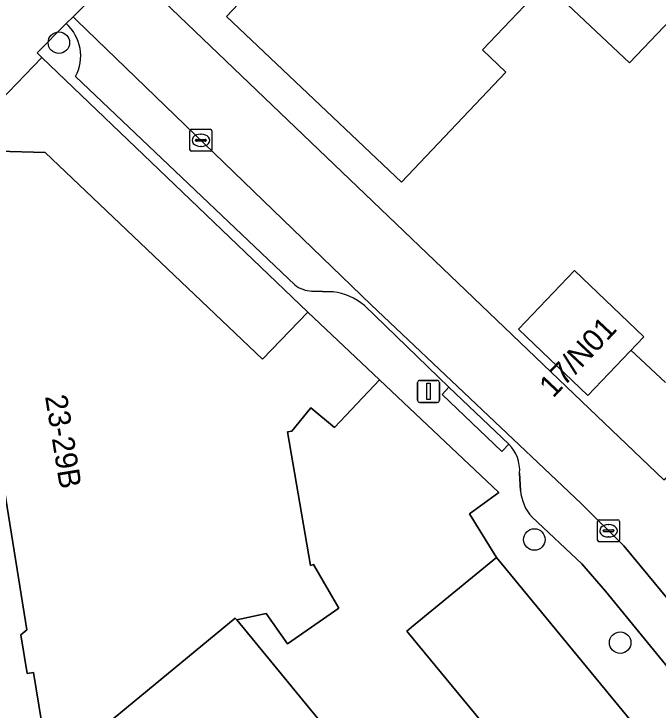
# Model space of a CAD drawing. Extents: x 160663 to 161506, y 382245 to 383291.
# Drawn here: x 160915.24 to 160944.54, y 383009.95 to 383041.61 of the extents above; entities that cross this region are included whole.
import ezdxf

# ---------------------------------------------------------------- set-up
doc = ezdxf.new("R2010")
doc.units = 0
for name, color, linetype in [('IMGEO_Boom', 7, 'Continuous'), ('IMGEO_Erf', 7, 'Continuous'), ('IMGEO_Hek', 7, 'Continuous'), ('IMGEO_Kolk', 7, 'Continuous'), ('IMGEO_Lichtmast', 7, 'Continuous'), ('IMGEO_Pand', 7, 'Continuous'), ('IMGEO_Pand_nummerreeks', 7, 'Continuous'), ('IMGEO_Parkeervlak_open', 7, 'Continuous'), ('IMGEO_Rijbaan_lokaal_open', 7, 'Continuous'), ('IMGEO_Voetpad_open', 7, 'Continuous')]:
    doc.layers.add(name, color=color, linetype=linetype)

msp = doc.modelspace()

# ---------------------------------------------------------------- linework, layer by layer
at = {"layer": 'IMGEO_Boom'}
for centre in [(160917.289, 383040.297), (160938.91, 383017.707), (160942.813, 383013.019)]:
    msp.add_circle(centre, 0.489, dxfattribs=at)
at = {"layer": 'IMGEO_Erf'}
for points in [[(160946.673, 383043.007), (160943.234, 383039.376), (160939.413, 383042.994), (160936.547, 383039.968), (160937.61, 383038.962), (160932.868, 383033.955), (160924.908, 383041.495), (160933.512, 383050.58)], [(160920.302, 383043.863), (160941.074, 383023.981), (160944.793, 383020.424), (160950.196, 383024.944), (160948.295, 383027.366), (160951.236, 383029.535), (160951.019, 383029.798), (160955.124, 383033.02), (160960.966, 383037.606), (160956.591, 383041.731)], [(160944.278, 383000), (160933.107, 383013.536), (160933.327, 383013.717), (160937.187, 383016.894), (160935.954, 383018.87), (160937.287, 383019.841), (160931.868, 383024.973), (160929.826, 383022.803), (160928.743, 383023.699), (160927.882, 383022.628), (160927.686, 383022.598), (160928.735, 383016.524), (160928.87, 383016.578), (160930.025, 383014.585), (160927.687, 383012.96), (160926.717, 383014.341), (160925.377, 383014.054), (160936.91, 383000)]]:
    msp.add_lwpolyline(points, dxfattribs=at)
for points in [[(160912.337, 383035.288), (160912.618, 383033.361), (160914.513, 383035.359), (160916.665, 383035.303), (160926.554, 383025.911), (160928.616, 383028.044), (160916.51, 383039.63)], [(160943.885, 383026.926), (160941.337, 383024.258), (160938.188, 383027.266), (160940.736, 383029.934)]]:
    msp.add_lwpolyline(points, close=True, dxfattribs=at)
at = {"layer": 'IMGEO_Hek'}
msp.add_lwpolyline([(160944.871, 383024.843), (160943.298, 383026.312)], dxfattribs=at)
at = {"layer": 'IMGEO_Kolk'}
for p, q in [((160923.248, 383035.433), (160923.248, 383036.285)), ((160923.323, 383036.359), (160924.175, 383036.359)), ((160924.249, 383036.285), (160924.249, 383035.433)), ((160923.55, 383035.902), (160923.948, 383035.902)), ((160923.736, 383036.139), (160923.761, 383036.139)), ((160923.507, 383035.853), (160923.507, 383035.865)), ((160923.945, 383035.816), (160923.547, 383035.816)), ((160923.759, 383035.579), (160923.734, 383035.579)), ((160923.991, 383035.865), (160923.991, 383035.853)), ((160924.175, 383035.359), (160923.323, 383035.359)), ((160941.782, 383017.68), (160941.782, 383018.532)), ((160941.857, 383018.606), (160942.709, 383018.606)), ((160942.783, 383018.532), (160942.783, 383017.68)), ((160942.084, 383018.149), (160942.482, 383018.149)), ((160942.27, 383018.386), (160942.295, 383018.386)), ((160942.041, 383018.1), (160942.041, 383018.112)), ((160942.479, 383018.063), (160942.081, 383018.063)), ((160942.525, 383018.112), (160942.525, 383018.1)), ((160942.709, 383017.606), (160941.857, 383017.606)), ((160942.293, 383017.826), (160942.268, 383017.826))]:
    msp.add_line(p, q, dxfattribs=at)
for points in [[(160923.248, 383035.433), (160923.248, 383036.285)], [(160923.323, 383036.359), (160924.175, 383036.359)], [(160924.249, 383036.285), (160924.249, 383035.433)], [(160924.175, 383035.359), (160923.323, 383035.359)], [(160941.782, 383017.68), (160941.782, 383018.532)], [(160941.857, 383018.606), (160942.709, 383018.606)], [(160942.783, 383018.532), (160942.783, 383017.68)], [(160942.709, 383017.606), (160941.857, 383017.606)]]:
    msp.add_lwpolyline(points, dxfattribs=at)
for centre, radius, start, end in [((160923.325, 383036.283), 0.0765, 91.552, 178.448), ((160923.325, 383036.283), 0.0765, 91.552, 178.448), ((160924.173, 383036.283), 0.0765, 1.552, 88.448), ((160924.173, 383036.283), 0.0765, 1.552, 88.448), ((160923.547, 383035.862), 0.0403, 85.8775, 175.7526), ((160923.952, 383035.864), 0.0386, 1.7309, 96.639), ((160923.544, 383035.852), 0.0366, 178.938, 274.7102), ((160923.948, 383035.859), 0.043, 264.8664, 352.4533), ((160923.325, 383035.435), 0.0765, 181.552, 268.448), ((160923.325, 383035.435), 0.0765, 181.552, 268.448), ((160924.173, 383035.435), 0.0765, 271.552, 358.448), ((160924.173, 383035.435), 0.0765, 271.552, 358.448), ((160941.859, 383018.53), 0.0765, 91.552, 178.448), ((160941.859, 383018.53), 0.0765, 91.552, 178.448), ((160942.707, 383018.53), 0.0765, 1.552, 88.448), ((160942.707, 383018.53), 0.0765, 1.552, 88.448), ((160942.081, 383018.109), 0.0403, 85.8775, 175.7526), ((160942.486, 383018.111), 0.0386, 1.7309, 96.639), ((160942.078, 383018.099), 0.0366, 178.938, 274.7102), ((160942.482, 383018.106), 0.043, 264.8664, 352.4533), ((160941.859, 383017.682), 0.0765, 181.552, 268.448), ((160941.859, 383017.682), 0.0765, 181.552, 268.448), ((160942.707, 383017.682), 0.0765, 271.552, 358.448), ((160942.707, 383017.682), 0.0765, 271.552, 358.448)]:
    msp.add_arc(centre, radius, start, end, dxfattribs=at)
for centre, major_axis, ratio, start_param, end_param in [((160923.735, 383035.859), (-0.387, 0.002), 0.722429, 4.712389, 7.853982), ((160923.76, 383035.859), (-0.39, 0.002), 0.717154, 1.570796, 4.712389), ((160942.269, 383018.106), (-0.387, 0.002), 0.722429, 4.712389, 7.853982), ((160942.294, 383018.106), (-0.39, 0.002), 0.717154, 1.570796, 4.712389)]:
    msp.add_ellipse(centre, major_axis=major_axis, ratio=ratio, start_param=start_param, end_param=end_param, dxfattribs=at)
at = {"layer": 'IMGEO_Lichtmast'}
for p, q in [((160933.603, 383024.042), (160933.603, 383024.842)), ((160933.603, 383024.842), (160933.603, 383024.042)), ((160933.703, 383024.942), (160934.493, 383024.942)), ((160934.493, 383024.942), (160933.703, 383024.942)), ((160934.593, 383024.842), (160934.593, 383024.042)), ((160934.593, 383024.042), (160934.593, 383024.842)), ((160934.493, 383023.942), (160933.703, 383023.942)), ((160933.703, 383023.942), (160934.493, 383023.942))]:
    msp.add_line(p, q, dxfattribs=at)
msp.add_lwpolyline([(160934.023, 383024.817), (160934.173, 383024.817), (160934.173, 383024.067), (160934.023, 383024.067), (160934.023, 383024.817)], dxfattribs=at)
for centre, start, end in [((160933.703, 383024.842), 90, 180), ((160933.703, 383024.842), 90, 180), ((160934.493, 383024.842), 0, 90), ((160934.493, 383024.842), 360, 90), ((160933.703, 383024.042), 180, 270), ((160933.703, 383024.042), 180, 270), ((160934.493, 383024.042), 270, 0), ((160934.493, 383024.042), 270, 0)]:
    msp.add_arc(centre, 0.1, start, end, dxfattribs=at)
at = {"layer": 'IMGEO_Pand'}
for points in [[(160947.026, 383050.883), (160936.597, 383060.955), (160936.469, 383060.82), (160934.625, 383058.872), (160938.155, 383055.529), (160934.601, 383051.776), (160934.746, 383051.638), (160933.701, 383050.535), (160933.512, 383050.58), (160924.908, 383041.495), (160932.868, 383033.955), (160937.61, 383038.962), (160936.547, 383039.968), (160939.413, 383042.994), (160943.234, 383039.376), (160946.673, 383043.007), (160947.525, 383043.907), (160943.779, 383047.455)], [(160941.337, 383024.258), (160943.885, 383026.926), (160940.736, 383029.934), (160938.188, 383027.266)], [(160970.046, 382977.114), (160951.094, 383000), (160937.187, 383016.894), (160933.327, 383013.717), (160933.107, 383013.536), (160944.278, 383000), (160965.948, 382973.741), (160966.186, 382973.937)], [(160936.91, 383000), (160925.377, 383014.054), (160925.308, 383014.138), (160917.332, 383007.56), (160917.629, 383007.213), (160923.54, 383000), (160953.589, 382963.329), (160961.617, 382969.937), (160958.423, 382973.784)]]:
    msp.add_lwpolyline(points, close=True, dxfattribs=at)
for points in [[(160917.332, 383007.56), (160925.308, 383014.138), (160925.377, 383014.054), (160926.717, 383014.341), (160927.687, 383012.96), (160930.025, 383014.585), (160928.87, 383016.578), (160928.735, 383016.524), (160927.686, 383022.598), (160927.882, 383022.628), (160928.743, 383023.699), (160929.826, 383022.803), (160931.868, 383024.973), (160928.616, 383028.044), (160926.554, 383025.911), (160916.665, 383035.303), (160914.513, 383035.359)], [(160914.599, 383021.167), (160915.834, 383013.595), (160915.566, 383013.376), (160915.853, 383011.614), (160916.14, 383011.661), (160916.747, 383007.941)]]:
    msp.add_lwpolyline(points, dxfattribs=at)
at = {"layer": 'IMGEO_Parkeervlak_open'}
for points in [[(160944.076, 383016.107), (160942.976, 383017.415), (160941.045, 383019.344), (160931.492, 383028.374), (160918.109, 383041.314), (160917.937, 383041.481), (160917.623, 383041.165)], [(160918.044, 383038.76), (160928.012, 383029.284)], [(160928.795, 383029.002), (160929.757, 383028.964)], [(160931.181, 383028.352), (160935.02, 383024.634), (160937.743, 383022.036)], [(160938.238, 383020.724), (160938.281, 383019.937)], [(160938.803, 383018.726), (160941.068, 383016.598), (160942.148, 383015.356), (160954.712, 383000), (160965.713, 382986.582), (160971.917, 382979.059), (160972.18, 382979.276), (160972.508, 382979.547), (160973.527, 382980.386), (160957.356, 383000), (160944.076, 383016.107)]]:
    msp.add_lwpolyline(points, dxfattribs=at)
for centre, radius, start, end in [((160916.315, 383039.697), 1.966, 331.5473, 48.311), ((160928.853, 383030.391), 1.39, 232.777, 267.6097), ((160929.424, 383026.225), 2.759, 50.4286, 83.0578), ((160936.585, 383020.85), 1.658, 355.6537, 45.688), ((160940.307, 383020.092), 2.032, 184.3808, 222.256)]:
    msp.add_arc(centre, radius, start, end, dxfattribs=at)
at = {"layer": 'IMGEO_Rijbaan_lokaal_open'}
msp.add_lwpolyline([(160944.793, 383020.424), (160941.074, 383023.981), (160920.302, 383043.863), (160917.937, 383041.481), (160918.109, 383041.314), (160931.492, 383028.374), (160941.045, 383019.344), (160942.976, 383017.415), (160944.076, 383016.107), (160957.356, 383000), (160973.527, 382980.386), (160972.508, 382979.547)], dxfattribs=at)
at = {"layer": 'IMGEO_Voetpad_open'}
for points in [[(160916.51, 383039.63), (160916.299, 383039.832), (160917.623, 383041.165), (160917.937, 383041.481), (160920.302, 383043.863), (160934.625, 383058.872), (160936.469, 383060.82), (160936.597, 383060.955), (160938.59, 383063.06), (160938.841, 383063), (160941.244, 383065.538), (160943.83, 383068.268), (160943.822, 383068.574), (160945.563, 383070.413), (160947.481, 383072.438), (160947.725, 383072.379), (160950.166, 383075.019), (160954.722, 383079.944), (160957.649, 383083.109), (160959.764, 383083.167), (160955.867, 383086.614)], [(160917.623, 383041.165), (160916.299, 383039.832), (160916.51, 383039.63), (160928.616, 383028.044), (160931.868, 383024.973), (160937.287, 383019.841), (160935.954, 383018.87), (160937.187, 383016.894), (160951.094, 383000), (160970.046, 382977.114), (160970.812, 382976.19), (160971.736, 382976.951), (160970.973, 382977.877), (160971.917, 382979.059), (160965.713, 382986.582), (160954.712, 383000), (160942.148, 383015.356), (160941.068, 383016.598), (160938.803, 383018.726)], [(160916.747, 383007.941), (160916.14, 383011.661), (160915.853, 383011.614), (160915.566, 383013.376), (160915.834, 383013.595), (160914.599, 383021.167), (160914.275, 383021.289), (160913.805, 383024.17), (160914.106, 383024.588), (160913.562, 383027.92), (160913.235, 383027.867), (160912.806, 383030.5), (160913.53, 383031.092), (160912.916, 383031.534), (160912.618, 383033.361), (160912.337, 383035.288), (160916.51, 383039.63)], [(160928.012, 383029.284), (160918.044, 383038.76)], [(160929.757, 383028.964), (160928.795, 383029.002)], [(160937.743, 383022.036), (160937.435, 383021.708), (160934.712, 383024.306), (160935.02, 383024.634), (160931.181, 383028.352)], [(160938.281, 383019.937), (160938.238, 383020.724)]]:
    msp.add_lwpolyline(points, dxfattribs=at)
msp.add_lwpolyline([(160935.02, 383024.634), (160934.712, 383024.306), (160937.435, 383021.708), (160937.743, 383022.036)], close=True, dxfattribs=at)
for centre, radius, start, end in [((160916.315, 383039.697), 1.966, 331.5473, 48.311), ((160928.853, 383030.391), 1.39, 232.777, 267.6097), ((160929.424, 383026.225), 2.759, 50.4286, 83.0578), ((160936.585, 383020.85), 1.658, 355.6537, 45.688), ((160940.307, 383020.092), 2.032, 184.3808, 222.256)]:
    msp.add_arc(centre, radius, start, end, dxfattribs=at)

# ---------------------------------------------------------------- texts
at = {"layer": 'IMGEO_Pand_nummerreeks'}
for s, rotation, p in [('17/N01', 46.7047, (160939.76, 383024.106)), ('23-29B', 279.226, (160916.656, 383024.219))]:
    msp.add_text(s, height=1, rotation=rotation, dxfattribs=at).set_placement(p)

doc.saveas('drawing.dxf')
